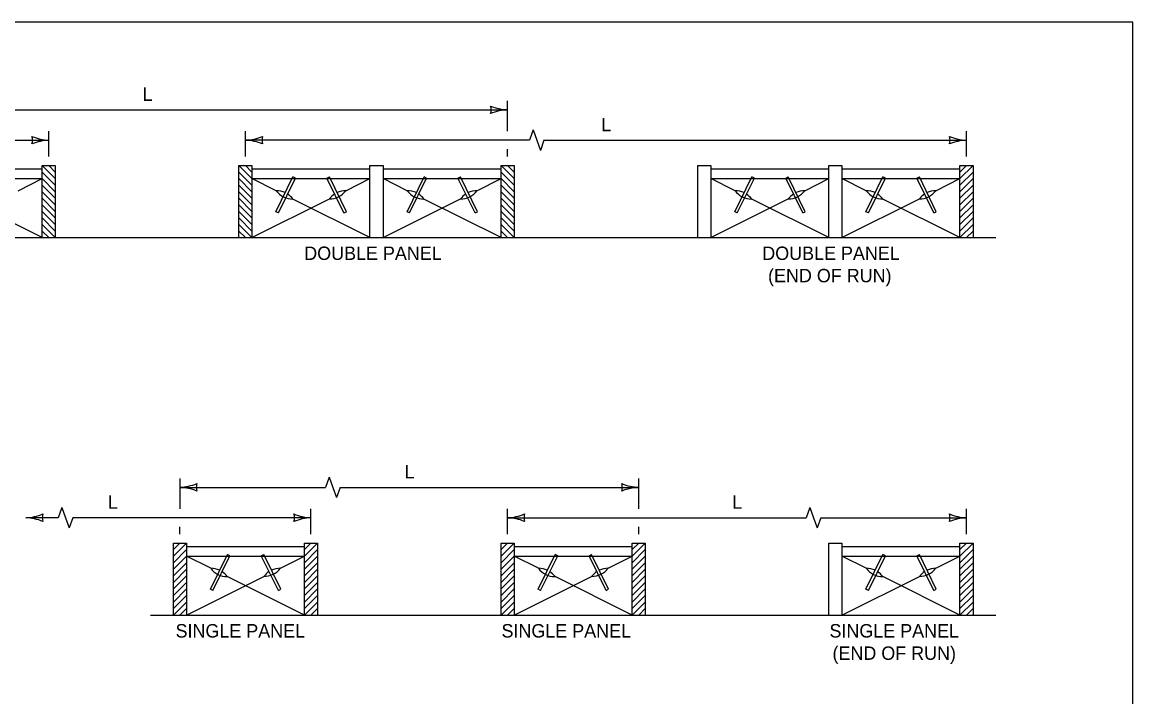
# Model space of a CAD drawing. Extents: x 49990.8 to 50021, y 49987.6 to 50011.4.
# Drawn here: x 50003.644 to 50008.615, y 50008.243 to 50011.263 of the extents above; entities that cross this region are included whole.
import ezdxf

# ---------------------------------------------------------------- set-up
doc = ezdxf.new("R2010")
doc.units = 0
for name, color, linetype in [('Level 1', 7, 'Continuous'), ('Level 2', 7, 'Continuous'), ('Level 3', 7, 'Continuous')]:
    doc.layers.add(name, color=color, linetype=linetype)

msp = doc.modelspace()

# ---------------------------------------------------------------- linework, layer by layer
at = {"layer": 'Level 1'}
for p, q in [((50003.2052, 50010.6067), (50003.7334, 50010.6067)), ((50003.7334, 50010.2986), (50003.7334, 50010.6214)), ((50003.7334, 50010.6214), (50003.792, 50010.6214)), ((50003.7334, 50010.6214), (50003.792, 50010.5627)), ((50003.7334, 50010.592), (50003.792, 50010.5334)), ((50003.7627, 50010.6214), (50003.792, 50010.592)), ((50003.792, 50010.6214), (50003.792, 50010.2986)), ((50004.6136, 50010.2986), (50004.6136, 50010.6214)), ((50004.6136, 50010.6214), (50004.6722, 50010.6214)), ((50004.6136, 50010.6214), (50004.6722, 50010.5627)), ((50004.6136, 50010.592), (50004.6722, 50010.5334)), ((50004.6429, 50010.6214), (50004.6722, 50010.592)), ((50004.6722, 50010.6214), (50004.6722, 50010.2986)), ((50004.6722, 50010.6067), (50005.2004, 50010.6067)), ((50005.2004, 50010.2986), (50005.2004, 50010.6214)), ((50005.2004, 50010.6214), (50005.259, 50010.6214)), ((50005.259, 50010.6214), (50005.259, 50010.2986)), ((50005.259, 50010.6067), (50005.7872, 50010.6067)), ((50005.7872, 50010.2986), (50005.7872, 50010.6214)), ((50005.7872, 50010.6214), (50005.8458, 50010.6214)), ((50005.7872, 50010.6214), (50005.8458, 50010.5627)), ((50005.7872, 50010.592), (50005.8458, 50010.5334)), ((50005.8165, 50010.6214), (50005.8458, 50010.592)), ((50005.8458, 50010.6214), (50005.8458, 50010.2986)), ((50006.6674, 50010.2986), (50006.6674, 50010.6214)), ((50006.6674, 50010.6214), (50006.726, 50010.6214)), ((50006.726, 50010.6214), (50006.726, 50010.2986)), ((50006.726, 50010.6067), (50007.2542, 50010.6067)), ((50007.2542, 50010.2986), (50007.2542, 50010.6214)), ((50007.2542, 50010.6214), (50007.3128, 50010.6214)), ((50007.3128, 50010.6214), (50007.3128, 50010.2986)), ((50007.3128, 50010.6067), (50007.841, 50010.6067)), ((50007.841, 50010.2986), (50007.841, 50010.6214)), ((50007.841, 50010.6214), (50007.8996, 50010.6214)), ((50007.841, 50010.5627), (50007.8996, 50010.6214)), ((50007.841, 50010.592), (50007.8703, 50010.6214)), ((50007.841, 50010.5334), (50007.8996, 50010.592)), ((50007.8996, 50010.6214), (50007.8996, 50010.2986)), ((50003.2052, 50010.5627), (50003.7334, 50010.5627)), ((50003.6255, 50010.5083), (50003.7334, 50010.5627)), ((50003.7334, 50010.5627), (50003.792, 50010.504)), ((50003.7334, 50010.5334), (50003.792, 50010.4747)), ((50004.6136, 50010.5627), (50004.6722, 50010.504)), ((50004.6136, 50010.5334), (50004.6722, 50010.4747)), ((50004.6722, 50010.5627), (50005.2004, 50010.5627)), ((50004.7807, 50010.5085), (50004.6722, 50010.5627)), ((50004.7796, 50010.4146), (50004.8555, 50010.57)), ((50004.7904, 50010.4091), (50004.867, 50010.5642)), ((50004.867, 50010.5642), (50004.8555, 50010.57)), ((50005.0074, 50010.5642), (50005.0189, 50010.57)), ((50005.0838, 50010.4091), (50005.0074, 50010.5642)), ((50005.0946, 50010.4146), (50005.0189, 50010.57)), ((50005.0925, 50010.5083), (50005.2004, 50010.5627)), ((50005.259, 50010.5627), (50005.7872, 50010.5627)), ((50005.3675, 50010.5085), (50005.259, 50010.5627)), ((50005.3664, 50010.4146), (50005.4423, 50010.57)), ((50005.3772, 50010.4091), (50005.4538, 50010.5642)), ((50005.4538, 50010.5642), (50005.4423, 50010.57)), ((50005.5942, 50010.5642), (50005.6057, 50010.57)), ((50005.6706, 50010.4091), (50005.5942, 50010.5642)), ((50005.6814, 50010.4146), (50005.6057, 50010.57)), ((50005.6793, 50010.5083), (50005.7872, 50010.5627)), ((50005.7872, 50010.5627), (50005.8458, 50010.504)), ((50005.7872, 50010.5334), (50005.8458, 50010.4747)), ((50006.726, 50010.5627), (50007.2542, 50010.5627)), ((50006.8345, 50010.5085), (50006.726, 50010.5627)), ((50006.8334, 50010.4146), (50006.9093, 50010.57)), ((50006.8442, 50010.4091), (50006.9208, 50010.5642)), ((50006.9208, 50010.5642), (50006.9093, 50010.57)), ((50007.0612, 50010.5642), (50007.0727, 50010.57)), ((50007.1376, 50010.4091), (50007.0612, 50010.5642)), ((50007.1484, 50010.4146), (50007.0727, 50010.57)), ((50007.1463, 50010.5083), (50007.2542, 50010.5627)), ((50007.3128, 50010.5627), (50007.841, 50010.5627)), ((50007.4213, 50010.5085), (50007.3128, 50010.5627)), ((50007.4202, 50010.4146), (50007.4961, 50010.57)), ((50007.431, 50010.4091), (50007.5076, 50010.5642)), ((50007.5076, 50010.5642), (50007.4961, 50010.57)), ((50007.648, 50010.5642), (50007.6595, 50010.57)), ((50007.7244, 50010.4091), (50007.648, 50010.5642)), ((50007.7352, 50010.4146), (50007.6595, 50010.57)), ((50007.7331, 50010.5083), (50007.841, 50010.5627)), ((50007.841, 50010.504), (50007.8996, 50010.5627)), ((50007.841, 50010.4747), (50007.8996, 50010.5334)), ((50003.7334, 50010.504), (50003.792, 50010.4453)), ((50004.6136, 50010.504), (50004.6722, 50010.4453)), ((50005.7872, 50010.504), (50005.8458, 50010.4453)), ((50007.841, 50010.4453), (50007.8996, 50010.504)), ((50003.7334, 50010.2986), (50003.388, 50010.4713)), ((50003.7334, 50010.4747), (50003.792, 50010.416)), ((50003.7334, 50010.4453), (50003.792, 50010.3867)), ((50004.6136, 50010.4747), (50004.6722, 50010.416)), ((50004.6136, 50010.4453), (50004.6722, 50010.3867)), ((50004.6722, 50010.2986), (50005.0189, 50010.4721)), ((50005.2004, 50010.2986), (50004.855, 50010.4713)), ((50005.259, 50010.2986), (50005.6057, 50010.4721)), ((50005.7872, 50010.2986), (50005.4418, 50010.4713)), ((50005.7872, 50010.4747), (50005.8458, 50010.416)), ((50005.7872, 50010.4453), (50005.8458, 50010.3867)), ((50006.726, 50010.2986), (50007.0727, 50010.4721)), ((50007.2542, 50010.2986), (50006.9088, 50010.4713)), ((50007.3128, 50010.2986), (50007.6595, 50010.4721)), ((50007.841, 50010.2986), (50007.4956, 50010.4713)), ((50007.841, 50010.416), (50007.8996, 50010.4747)), ((50007.841, 50010.3867), (50007.8996, 50010.4453)), ((50003.7334, 50010.416), (50003.792, 50010.3573)), ((50003.7334, 50010.3867), (50003.792, 50010.328)), ((50004.6136, 50010.416), (50004.6722, 50010.3573)), ((50004.6136, 50010.3867), (50004.6722, 50010.328)), ((50004.7904, 50010.4091), (50004.7796, 50010.4146)), ((50005.0838, 50010.4091), (50005.0946, 50010.4146)), ((50005.3772, 50010.4091), (50005.3664, 50010.4146)), ((50005.6706, 50010.4091), (50005.6814, 50010.4146)), ((50005.7872, 50010.416), (50005.8458, 50010.3573)), ((50005.7872, 50010.3867), (50005.8458, 50010.328)), ((50006.8442, 50010.4091), (50006.8334, 50010.4146)), ((50007.1376, 50010.4091), (50007.1484, 50010.4146)), ((50007.431, 50010.4091), (50007.4202, 50010.4146)), ((50007.7244, 50010.4091), (50007.7352, 50010.4146)), ((50007.841, 50010.3573), (50007.8996, 50010.416)), ((50007.841, 50010.328), (50007.8996, 50010.3867)), ((50003.7334, 50010.3573), (50003.792, 50010.2986)), ((50004.6136, 50010.3573), (50004.6722, 50010.2986)), ((50005.7872, 50010.3573), (50005.8458, 50010.2986)), ((50007.841, 50010.2986), (50007.8996, 50010.3573)), ((50000.9901, 50010.2986), (50008.0023, 50010.2986)), ((50003.7334, 50010.328), (50003.7627, 50010.2986)), ((50004.6136, 50010.328), (50004.6429, 50010.2986)), ((50005.7872, 50010.328), (50005.8165, 50010.2986)), ((50007.8703, 50010.2986), (50007.8996, 50010.328)), ((50004.3202, 50008.6086), (50004.3202, 50008.9314)), ((50004.3202, 50008.9314), (50004.3788, 50008.9314)), ((50004.3202, 50008.8727), (50004.3788, 50008.9314)), ((50004.3202, 50008.902), (50004.3495, 50008.9314)), ((50004.3202, 50008.8434), (50004.3788, 50008.902)), ((50004.3788, 50008.9314), (50004.3788, 50008.6086)), ((50004.3788, 50008.9167), (50004.907, 50008.9167)), ((50004.907, 50008.6086), (50004.907, 50008.9314)), ((50004.907, 50008.9314), (50004.9656, 50008.9314)), ((50004.907, 50008.8727), (50004.9656, 50008.9314)), ((50004.907, 50008.902), (50004.9363, 50008.9314)), ((50004.907, 50008.8434), (50004.9656, 50008.902)), ((50004.9656, 50008.9314), (50004.9656, 50008.6086)), ((50005.7872, 50008.6086), (50005.7872, 50008.9314)), ((50005.7872, 50008.9314), (50005.8458, 50008.9314)), ((50005.7872, 50008.8727), (50005.8458, 50008.9314)), ((50005.7872, 50008.902), (50005.8165, 50008.9314)), ((50005.7872, 50008.8434), (50005.8458, 50008.902)), ((50005.8458, 50008.9314), (50005.8458, 50008.6086)), ((50005.8458, 50008.9167), (50006.374, 50008.9167)), ((50006.374, 50008.6086), (50006.374, 50008.9314)), ((50006.374, 50008.9314), (50006.4326, 50008.9314)), ((50006.374, 50008.8727), (50006.4326, 50008.9314)), ((50006.374, 50008.902), (50006.4033, 50008.9314)), ((50006.374, 50008.8434), (50006.4326, 50008.902)), ((50006.4326, 50008.9314), (50006.4326, 50008.6086)), ((50007.2542, 50008.6086), (50007.2542, 50008.9314)), ((50007.2542, 50008.9314), (50007.3128, 50008.9314)), ((50007.3128, 50008.9314), (50007.3128, 50008.6086)), ((50007.3128, 50008.9167), (50007.841, 50008.9167)), ((50007.841, 50008.6086), (50007.841, 50008.9314)), ((50007.841, 50008.9314), (50007.8996, 50008.9314)), ((50007.841, 50008.8727), (50007.8996, 50008.9314)), ((50007.841, 50008.902), (50007.8703, 50008.9314)), ((50007.841, 50008.8434), (50007.8996, 50008.902)), ((50007.8996, 50008.9314), (50007.8996, 50008.6086)), ((50004.3202, 50008.814), (50004.3788, 50008.8727)), ((50004.3202, 50008.7847), (50004.3788, 50008.8434)), ((50004.3788, 50008.8727), (50004.907, 50008.8727)), ((50004.4873, 50008.8185), (50004.3788, 50008.8727)), ((50004.4862, 50008.7246), (50004.5621, 50008.88)), ((50004.497, 50008.7191), (50004.5736, 50008.8742)), ((50004.5736, 50008.8742), (50004.5621, 50008.88)), ((50004.714, 50008.8742), (50004.7255, 50008.88)), ((50004.7904, 50008.7191), (50004.714, 50008.8742)), ((50004.8012, 50008.7246), (50004.7255, 50008.88)), ((50004.7991, 50008.8184), (50004.907, 50008.8727)), ((50004.907, 50008.814), (50004.9656, 50008.8727)), ((50004.907, 50008.7847), (50004.9656, 50008.8434)), ((50005.7872, 50008.814), (50005.8458, 50008.8727)), ((50005.7872, 50008.7847), (50005.8458, 50008.8434)), ((50005.8458, 50008.8727), (50006.374, 50008.8727)), ((50005.9543, 50008.8185), (50005.8458, 50008.8727)), ((50005.9532, 50008.7246), (50006.0291, 50008.88)), ((50005.964, 50008.7191), (50006.0406, 50008.8742)), ((50006.0406, 50008.8742), (50006.0291, 50008.88)), ((50006.181, 50008.8742), (50006.1925, 50008.88)), ((50006.2574, 50008.7191), (50006.181, 50008.8742)), ((50006.2682, 50008.7246), (50006.1925, 50008.88)), ((50006.2661, 50008.8184), (50006.374, 50008.8727)), ((50006.374, 50008.814), (50006.4326, 50008.8727)), ((50006.374, 50008.7847), (50006.4326, 50008.8434)), ((50007.3128, 50008.8727), (50007.841, 50008.8727)), ((50007.4213, 50008.8185), (50007.3128, 50008.8727)), ((50007.4202, 50008.7246), (50007.4961, 50008.88)), ((50007.431, 50008.7191), (50007.5076, 50008.8742)), ((50007.5076, 50008.8742), (50007.4961, 50008.88)), ((50007.648, 50008.8742), (50007.6595, 50008.88)), ((50007.7244, 50008.7191), (50007.648, 50008.8742)), ((50007.7352, 50008.7246), (50007.6595, 50008.88)), ((50007.7331, 50008.8184), (50007.841, 50008.8727)), ((50007.841, 50008.814), (50007.8996, 50008.8727)), ((50007.841, 50008.7847), (50007.8996, 50008.8434)), ((50004.3202, 50008.7553), (50004.3788, 50008.814)), ((50004.907, 50008.7553), (50004.9656, 50008.814)), ((50005.7872, 50008.7553), (50005.8458, 50008.814)), ((50006.374, 50008.7553), (50006.4326, 50008.814)), ((50007.841, 50008.7553), (50007.8996, 50008.814)), ((50004.3202, 50008.726), (50004.3788, 50008.7847)), ((50004.3202, 50008.6967), (50004.3788, 50008.7553)), ((50004.3788, 50008.6086), (50004.7255, 50008.7821)), ((50004.907, 50008.6086), (50004.5616, 50008.7813)), ((50004.907, 50008.726), (50004.9656, 50008.7847)), ((50004.907, 50008.6967), (50004.9656, 50008.7553)), ((50005.7872, 50008.726), (50005.8458, 50008.7847)), ((50005.7872, 50008.6967), (50005.8458, 50008.7553)), ((50005.8458, 50008.6086), (50006.1925, 50008.7821)), ((50006.374, 50008.6086), (50006.0286, 50008.7813)), ((50006.374, 50008.726), (50006.4326, 50008.7847)), ((50006.374, 50008.6967), (50006.4326, 50008.7553)), ((50007.3128, 50008.6086), (50007.6595, 50008.7821)), ((50007.841, 50008.6086), (50007.4956, 50008.7813)), ((50007.841, 50008.726), (50007.8996, 50008.7847)), ((50007.841, 50008.6967), (50007.8996, 50008.7553)), ((50004.3202, 50008.6673), (50004.3788, 50008.726)), ((50004.3202, 50008.638), (50004.3788, 50008.6967)), ((50004.497, 50008.7191), (50004.4862, 50008.7246)), ((50004.7904, 50008.7191), (50004.8012, 50008.7246)), ((50004.907, 50008.6673), (50004.9656, 50008.726)), ((50004.907, 50008.638), (50004.9656, 50008.6967)), ((50005.7872, 50008.6673), (50005.8458, 50008.726)), ((50005.7872, 50008.638), (50005.8458, 50008.6967)), ((50005.964, 50008.7191), (50005.9532, 50008.7246)), ((50006.2574, 50008.7191), (50006.2682, 50008.7246)), ((50006.374, 50008.6673), (50006.4326, 50008.726)), ((50006.374, 50008.638), (50006.4326, 50008.6967)), ((50007.431, 50008.7191), (50007.4202, 50008.7246)), ((50007.7244, 50008.7191), (50007.7352, 50008.7246)), ((50007.841, 50008.6673), (50007.8996, 50008.726)), ((50007.841, 50008.638), (50007.8996, 50008.6967)), ((50004.3202, 50008.6086), (50004.3788, 50008.6673)), ((50004.907, 50008.6086), (50004.9656, 50008.6673)), ((50005.7872, 50008.6086), (50005.8458, 50008.6673)), ((50006.374, 50008.6086), (50006.4326, 50008.6673)), ((50007.841, 50008.6086), (50007.8996, 50008.6673)), ((50004.2174, 50008.6086), (50008.0023, 50008.6086)), ((50004.3495, 50008.6086), (50004.3788, 50008.638)), ((50004.9363, 50008.6086), (50004.9656, 50008.638)), ((50005.8165, 50008.6086), (50005.8458, 50008.638)), ((50006.4033, 50008.6086), (50006.4326, 50008.638)), ((50007.8703, 50008.6086), (50007.8996, 50008.638))]:
    msp.add_line(p, q, dxfattribs=at)
msp.add_lwpolyline([(50008.6146, 50011.2628), (50000.3356, 50011.2628), (50000.3356, 50000.0624), (50008.6146, 50000.0624)], close=True, dxfattribs=at)
for centre, start, end in [((50004.8541, 50010.5623), 216.2498, 270.5589), ((50004.7824, 50010.4175), 64.7782, 91.0797), ((50004.7823, 50010.4166), 36.9715, 57.0474), ((50005.0198, 50010.563), 269.4347, 323.0285), ((50005.0916, 50010.4174), 122.9663, 143.0376), ((50005.0916, 50010.4174), 89.4411, 115.0561), ((50005.4409, 50010.5623), 216.2498, 270.5589), ((50005.3692, 50010.4175), 64.7782, 91.0797), ((50005.3691, 50010.4166), 36.9715, 57.0474), ((50005.6066, 50010.563), 269.4347, 323.0285), ((50005.6784, 50010.4174), 122.9663, 143.0376), ((50005.6784, 50010.4174), 89.4411, 115.0561), ((50006.9079, 50010.5623), 216.2498, 270.5589), ((50006.8362, 50010.4175), 64.7782, 91.0797), ((50006.8361, 50010.4166), 36.9715, 57.0474), ((50007.0736, 50010.563), 269.4347, 323.0285), ((50007.1454, 50010.4174), 122.9663, 143.0376), ((50007.1454, 50010.4174), 89.4411, 115.0561), ((50007.4947, 50010.5623), 216.2498, 270.5589), ((50007.423, 50010.4175), 64.7782, 91.0797), ((50007.4229, 50010.4166), 36.9715, 57.0474), ((50007.6604, 50010.563), 269.4347, 323.0285), ((50007.7322, 50010.4174), 122.9663, 143.0376), ((50007.7322, 50010.4174), 89.4411, 115.0561), ((50004.5607, 50008.8723), 216.2498, 270.5589), ((50004.489, 50008.7275), 64.7782, 91.0797), ((50004.4889, 50008.7266), 36.9715, 57.0474), ((50004.7264, 50008.8731), 269.4347, 323.0285), ((50004.7982, 50008.7274), 122.9663, 143.0376), ((50004.7982, 50008.7274), 89.4411, 115.0561), ((50006.0277, 50008.8723), 216.2498, 270.5589), ((50005.956, 50008.7275), 64.7782, 91.0797), ((50005.9559, 50008.7266), 36.9715, 57.0474), ((50006.1934, 50008.8731), 269.4347, 323.0285), ((50006.2652, 50008.7274), 122.9663, 143.0376), ((50006.2652, 50008.7274), 89.4411, 115.0561), ((50007.4947, 50008.8723), 216.2498, 270.5589), ((50007.423, 50008.7275), 64.7782, 91.0797), ((50007.4229, 50008.7266), 36.9715, 57.0474), ((50007.6604, 50008.8731), 269.4347, 323.0285), ((50007.7322, 50008.7274), 122.9663, 143.0376), ((50007.7322, 50008.7274), 89.4411, 115.0561)]:
    msp.add_arc(centre, 0.091, start, end, dxfattribs=at)
at = {"layer": 'Level 3'}
for p, q in [((50005.8164, 50010.7747), (50005.8164, 50010.9108)), ((50003.306, 50010.8708), (50005.8164, 50010.8708)), ((50005.9306, 50010.7804), (50005.9144, 50010.7347)), ((50005.9306, 50010.7804), (50005.9468, 50010.7347)), ((50001.8394, 50010.7347), (50003.7636, 50010.7347)), ((50003.7636, 50010.6614), (50003.7636, 50010.7747)), ((50004.6438, 50010.6614), (50004.6438, 50010.7747)), ((50005.9144, 50010.7347), (50004.6438, 50010.7347)), ((50005.9468, 50010.7347), (50005.963, 50010.689)), ((50005.9792, 50010.7347), (50005.963, 50010.689)), ((50005.9792, 50010.7347), (50007.8703, 50010.7347)), ((50007.8703, 50010.6614), (50007.8703, 50010.7747)), ((50005.8164, 50010.6614), (50005.8164, 50010.6947)), ((50004.3494, 50009.2208), (50004.3494, 50009.0847)), ((50005.0178, 50009.2265), (50005.0016, 50009.1808)), ((50005.0178, 50009.2265), (50005.034, 50009.1808)), ((50006.4032, 50009.0847), (50006.4032, 50009.2208)), ((50004.3494, 50009.1808), (50005.0016, 50009.1808)), ((50005.034, 50009.1808), (50005.0502, 50009.1351)), ((50005.0664, 50009.1808), (50005.0502, 50009.1351)), ((50005.0664, 50009.1808), (50006.4032, 50009.1808)), ((50003.8214, 50009.0904), (50003.8052, 50009.0447)), ((50003.8214, 50009.0904), (50003.8376, 50009.0447)), ((50007.1694, 50009.0904), (50007.1532, 50009.0447)), ((50007.1694, 50009.0904), (50007.1856, 50009.0447)), ((50003.8052, 50009.0447), (50003.66, 50009.0447)), ((50003.8376, 50009.0447), (50003.8538, 50008.999)), ((50003.87, 50009.0447), (50003.8538, 50008.999)), ((50004.9362, 50009.0447), (50003.87, 50009.0447)), ((50004.9362, 50008.9714), (50004.9362, 50009.0847)), ((50005.8164, 50008.9714), (50005.8164, 50009.0847)), ((50005.8164, 50009.0447), (50007.1532, 50009.0447)), ((50007.1856, 50009.0447), (50007.2018, 50008.999)), ((50007.218, 50009.0447), (50007.2018, 50008.999)), ((50007.218, 50009.0447), (50007.8702, 50009.0447)), ((50007.8702, 50008.9714), (50007.8702, 50009.0847)), ((50004.3495, 50008.9714), (50004.3495, 50009.0047)), ((50006.4032, 50008.9714), (50006.4032, 50009.0047))]:
    msp.add_line(p, q, dxfattribs=at)
for centre, radius, start, end in [((50005.8255, 50011.0929), 0.2223, 247.456, 267.6395), ((50005.6881, 50010.8708), 0.0548, 342.1388, 17.8612), ((50005.8278, 50010.6381), 0.233, 92.8273, 112.0772), ((50003.7727, 50010.9568), 0.2223, 247.456, 267.6395), ((50003.6353, 50010.7347), 0.0548, 342.1388, 17.8612), ((50003.775, 50010.502), 0.233, 92.8273, 112.0772), ((50004.6323, 50010.9674), 0.233, 272.8273, 292.0772), ((50004.6346, 50010.5125), 0.2223, 67.456, 87.6395), ((50004.772, 50010.7347), 0.0548, 162.1388, 197.8612), ((50007.8794, 50010.9568), 0.2223, 247.456, 267.6395), ((50007.742, 50010.7347), 0.0548, 342.1388, 17.8612), ((50007.8817, 50010.502), 0.233, 92.8273, 112.0772), ((50004.3379, 50009.4135), 0.233, 272.8273, 292.0772), ((50004.4776, 50009.1808), 0.0548, 162.1388, 197.8612), ((50006.4123, 50009.4029), 0.2223, 247.456, 267.6395), ((50006.2749, 50009.1808), 0.0548, 342.1388, 17.8612), ((50004.3402, 50008.9587), 0.2223, 67.456, 87.6395), ((50006.4146, 50008.9481), 0.233, 92.8273, 112.0772), ((50003.6485, 50009.2774), 0.233, 272.8273, 292.0772), ((50003.6508, 50008.8226), 0.2223, 67.456, 87.6395), ((50003.7882, 50009.0447), 0.0548, 162.1388, 197.8612), ((50004.9453, 50009.2668), 0.2223, 247.456, 267.6395), ((50004.8079, 50009.0447), 0.0548, 342.1388, 17.8612), ((50004.9476, 50008.812), 0.233, 92.8273, 112.0772), ((50005.8049, 50009.2774), 0.233, 272.8273, 292.0772), ((50005.8072, 50008.8226), 0.2223, 67.456, 87.6395), ((50005.9446, 50009.0447), 0.0548, 162.1388, 197.8612), ((50007.8793, 50009.2668), 0.2223, 247.456, 267.6395), ((50007.7419, 50009.0447), 0.0548, 342.1388, 17.8612), ((50007.8816, 50008.812), 0.233, 92.8273, 112.0772)]:
    msp.add_arc(centre, radius, start, end, dxfattribs=at)

# ---------------------------------------------------------------- texts
at = {"layer": 'Level 2'}
for s, p in [('L', (50004.182, 50010.9108)), ('L', (50006.2358, 50010.7747)), ('DOUBLE PANEL', (50004.9061, 50010.1986)), ('DOUBLE PANEL', (50006.9562, 50010.1986)), ('(END OF RUN)', (50006.9821, 50010.0986)), ('L', (50005.3551, 50009.2208)), ('L', (50004.0276, 50009.0847)), ('L', (50006.8221, 50009.0847)), ('SINGLE PANEL', (50004.3301, 50008.5086)), ('SINGLE PANEL', (50005.789, 50008.5086)), ('SINGLE PANEL', (50007.257, 50008.5086)), ('(END OF RUN)', (50007.2705, 50008.4086))]:
    msp.add_text(s, height=0.06, dxfattribs=at).set_placement(p)

doc.saveas('drawing.dxf')
